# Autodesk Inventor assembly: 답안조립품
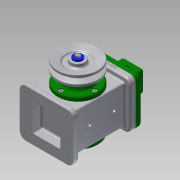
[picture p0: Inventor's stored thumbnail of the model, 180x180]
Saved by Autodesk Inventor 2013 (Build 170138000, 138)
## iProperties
Created: 2017-08
Part Number: 답안조립품
Document SubType Name: Assembly
Designer: Administrator
Author: Administrator
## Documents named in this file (18)
- C:\Users\Administrator\Desktop\470808V1012\답안조립품.iam
- C:\Users\Administrator\Desktop\470808V1012\본체.ipt
- C:\Users\Administrator\Desktop\470808V1012\편심축.ipt
- C:\Users\Administrator\Desktop\470808V1012\베어링 17 x 40 x 12.ipt
- C:\Users\Administrator\Desktop\470808V1012\뒤커버.ipt
- C:\Users\Administrator\Desktop\470808V1012\볼트 M4 x 8.ipt
- C:\Users\Administrator\Desktop\470808V1012\앞커버.ipt
- C:\Users\Administrator\Desktop\470808V1012\슬라이더.ipt
- C:\Users\Administrator\Desktop\470808V1012\링크.ipt
- C:\Users\Administrator\Desktop\470808V1012\클레비스 핀 6 x 22.ipt
- 클레비스 핀 6 x 22.ipt
- C:\Users\Administrator\Desktop\470808V1012\E-링.ipt
- C:\Users\Administrator\Desktop\470808V1012\덮개.ipt
- C:\Users\Administrator\Desktop\470808V1012\오일 실 17 30 8.ipt
- C:\Users\Administrator\Desktop\470808V1012\V-벨트풀리.ipt
- C:\Users\Administrator\Desktop\470808V1012\키 4 x 4 x 12.ipt
- C:\Users\Administrator\Desktop\470808V1012\와셔 4x16.ipt
- C:\Users\Administrator\Desktop\470808V1012\볼트 M4 x 10.ipt
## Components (2 placed, 2 different names)
1. E-링:1
2. V-벨트풀리:1
